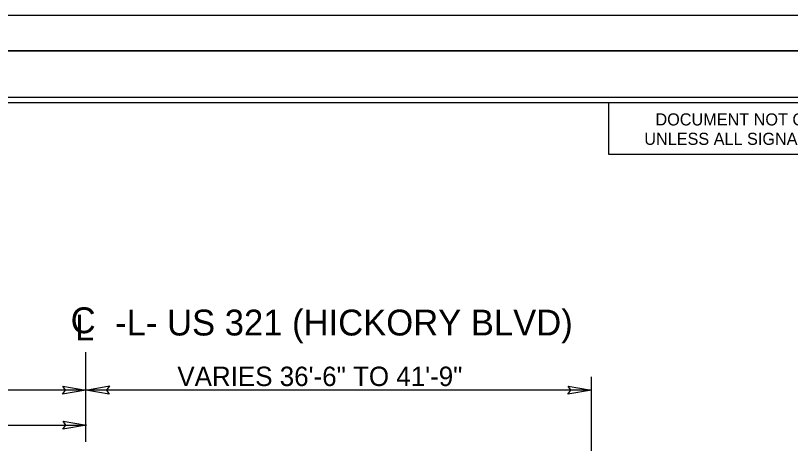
# Model space of a CAD drawing. Extents: x 2294455 to 2294795, y 719276 to 719941.
# Drawn here: x 2294647.9 to 2294722.8, y 719677.4 to 719718.8 of the extents above; entities that cross this region are included whole.
import ezdxf

# ---------------------------------------------------------------- set-up
doc = ezdxf.new("R2010")
doc.units = 0
for name, color, linetype in [('Default', 7, 'Continuous'), ('Old_Level_11', 7, 'Continuous'), ('Old_Level_2', 7, 'Continuous'), ('Old_Level_3', 7, 'Continuous'), ('Sheet Plot Border Inside CELL', 7, 'Continuous'), ('Sheet Plot Border Outside CELL', 7, 'Continuous'), ('Sheet Sticker Exception Certification CELL', 7, 'Continuous'), ('Sheet Typical CELL', 7, 'Continuous')]:
    doc.layers.add(name, color=color, linetype=linetype)

msp = doc.modelspace()

# ---------------------------------------------------------------- linework, layer by layer
at = {"layer": 'Default'}
msp.add_lwpolyline([(2294454.524, 719715.329), (2294794.524, 719715.329), (2294794.524, 719495.329), (2294454.524, 719495.329)], close=True, dxfattribs=at)
at = {"layer": 'Old_Level_11'}
for p, q in [((2294703.592, 719653.409), (2294703.592, 719683.835)), ((2294703.592, 719682.554), (2294605.982, 719682.553)), ((2294635.129, 719679.162), (2294654.759, 719679.158))]:
    msp.add_line(p, q, dxfattribs=at)
for points in [[(2294652.509, 719682.941), (2294654.759, 719682.553), (2294652.497, 719682.153), (2294652.784, 719682.553)], [(2294657.009, 719682.166), (2294654.759, 719682.553), (2294657.022, 719682.953), (2294656.734, 719682.553)], [(2294701.342, 719682.941), (2294703.592, 719682.554), (2294701.33, 719682.154), (2294701.617, 719682.554)], [(2294652.546, 719679.552), (2294654.796, 719679.165), (2294652.534, 719678.765), (2294652.821, 719679.165)]]:
    msp.add_lwpolyline(points, close=True, dxfattribs=at)
at = {"layer": 'Old_Level_2'}
for p, q in [((2294654.759, 719684.284), (2294654.759, 719686.211)), ((2294654.759, 719677.548), (2294654.759, 719684.284))]:
    msp.add_line(p, q, dxfattribs=at)
at = {"layer": 'Sheet Plot Border Inside CELL'}
msp.add_lwpolyline([(2294790.424, 719710.839), (2294457.124, 719710.839), (2294457.124, 719499.819), (2294790.424, 719499.819)], close=True, dxfattribs=at)
at = {"layer": 'Sheet Plot Border Outside CELL'}
for points in [[(2294793.79, 719718.758), (2294456.99, 719718.758), (2294456.99, 719498.758), (2294793.79, 719498.758)], [(2294794.524, 719715.329), (2294454.524, 719715.329), (2294454.524, 719495.329), (2294794.524, 719495.329)]]:
    msp.add_lwpolyline(points, close=True, dxfattribs=at)
at = {"layer": 'Sheet Sticker Exception Certification CELL'}
for p, q in [((2294705.291, 719705.325), (2294705.291, 719710.332)), ((2294705.291, 719710.332), (2294747.914, 719710.332)), ((2294747.914, 719705.325), (2294705.291, 719705.325))]:
    msp.add_line(p, q, dxfattribs=at)
at = {"layer": 'Sheet Typical CELL'}
msp.add_lwpolyline([(2294787.924, 719710.329), (2294487.924, 719710.329), (2294487.924, 719500.329), (2294787.924, 719500.329)], close=True, dxfattribs=at)

# ---------------------------------------------------------------- texts
at = {"layer": 'Old_Level_11'}
msp.add_text('VARIES 36\'-6" TO 41\'-9"', height=1.875, rotation=359.99996, dxfattribs=at).set_placement((2294663.586, 719682.938))
at = {"layer": 'Old_Level_2'}
for s, rotation, p in [('C', 359.99996, (2294653.278, 719688.046)), ('L', 359.94686, (2294653.704, 719687.346))]:
    msp.add_text(s, height=2.5, rotation=rotation, dxfattribs=at).set_placement(p)
at = {"layer": 'Old_Level_3'}
for s in ['-L- US 321 (HICKORY BLVD)', '-L-']:
    msp.add_text(s, height=2.5, rotation=0, dxfattribs=at).set_placement((2294657.579, 719687.825))
at = {"layer": 'Sheet Sticker Exception Certification CELL'}
for s, p in [('DOCUMENT NOT CONSIDERED FINAL', (2294709.781, 719708.128)), ('UNLESS ALL SIGNATURES COMPLETED', (2294708.7, 719706.252))]:
    msp.add_text(s, height=1.17193, dxfattribs=at).set_placement(p)

doc.saveas('drawing.dxf')
